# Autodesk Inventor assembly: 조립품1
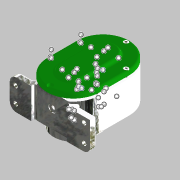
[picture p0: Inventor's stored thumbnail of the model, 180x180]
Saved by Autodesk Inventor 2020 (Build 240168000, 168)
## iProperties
Created: 2021-05
Part Number: 조립품1
Document SubType Name: Assembly
Designer: Owner
Mass: 766.482 g
Surface Area: 1127.05 cm^2
Volume: 376.133 cm^3
Density: 2.03779 g/cm^3
Author: Owner
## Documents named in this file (14)
- C:\Users\Owner\Desktop\710507V1016\710507V1016\조립품1.iam
- C:\Users\Owner\Desktop\710507V1016\710507V1016\본체.ipt
- C:\Users\Owner\Desktop\710507V1016\710507V1016\축 A.ipt
- C:\Users\Owner\Desktop\710507V1016\710507V1016\베어링 6002.ipt
- 베어링 6002.ipt
- C:\Users\Owner\Desktop\710507V1016\710507V1016\베어링 6001.ipt
- 베어링 6001.ipt
- C:\Users\Owner\Desktop\710507V1016\710507V1016\키 5 x 5 x 12.ipt
- C:\Users\Owner\Desktop\710507V1016\710507V1016\축 B.ipt
- C:\Users\Owner\Desktop\710507V1016\710507V1016\키 4 x 4 x 12.ipt
- C:\Users\Owner\Desktop\710507V1016\710507V1016\오일 실 12 22 7.ipt
- C:\Users\Owner\Desktop\710507V1016\710507V1016\커버 B.ipt
- C:\Users\Owner\Desktop\710507V1016\710507V1016\볼트 M4.ipt
- C:\Users\Owner\Desktop\710507V1016\710507V1016\커버 A.ipt
